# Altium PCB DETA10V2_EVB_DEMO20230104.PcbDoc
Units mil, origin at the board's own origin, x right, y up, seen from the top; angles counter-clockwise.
Board outline 1164.03 x 1653.03 mil, 2 copper layers (Top Layer, Bottom Layer), stack 61.855 mil thick; 50 components, 41 nets, 190 pads, 76 vias.
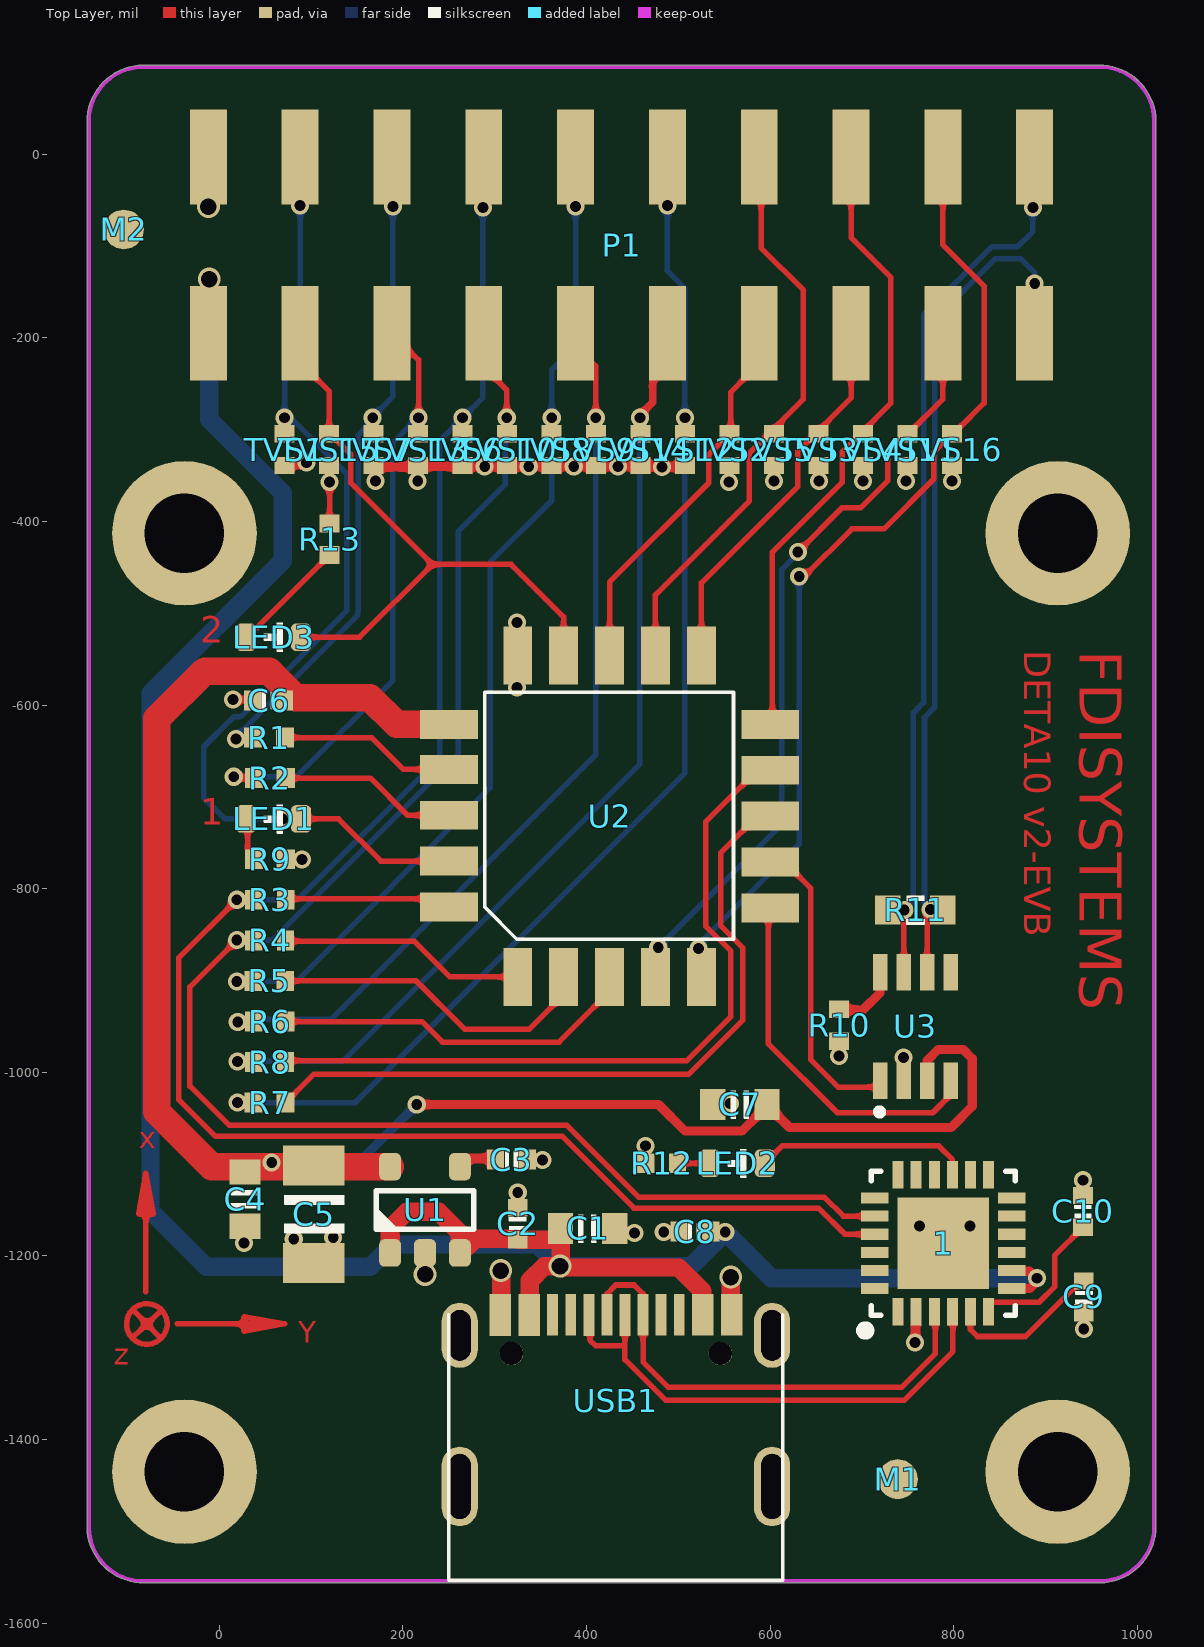
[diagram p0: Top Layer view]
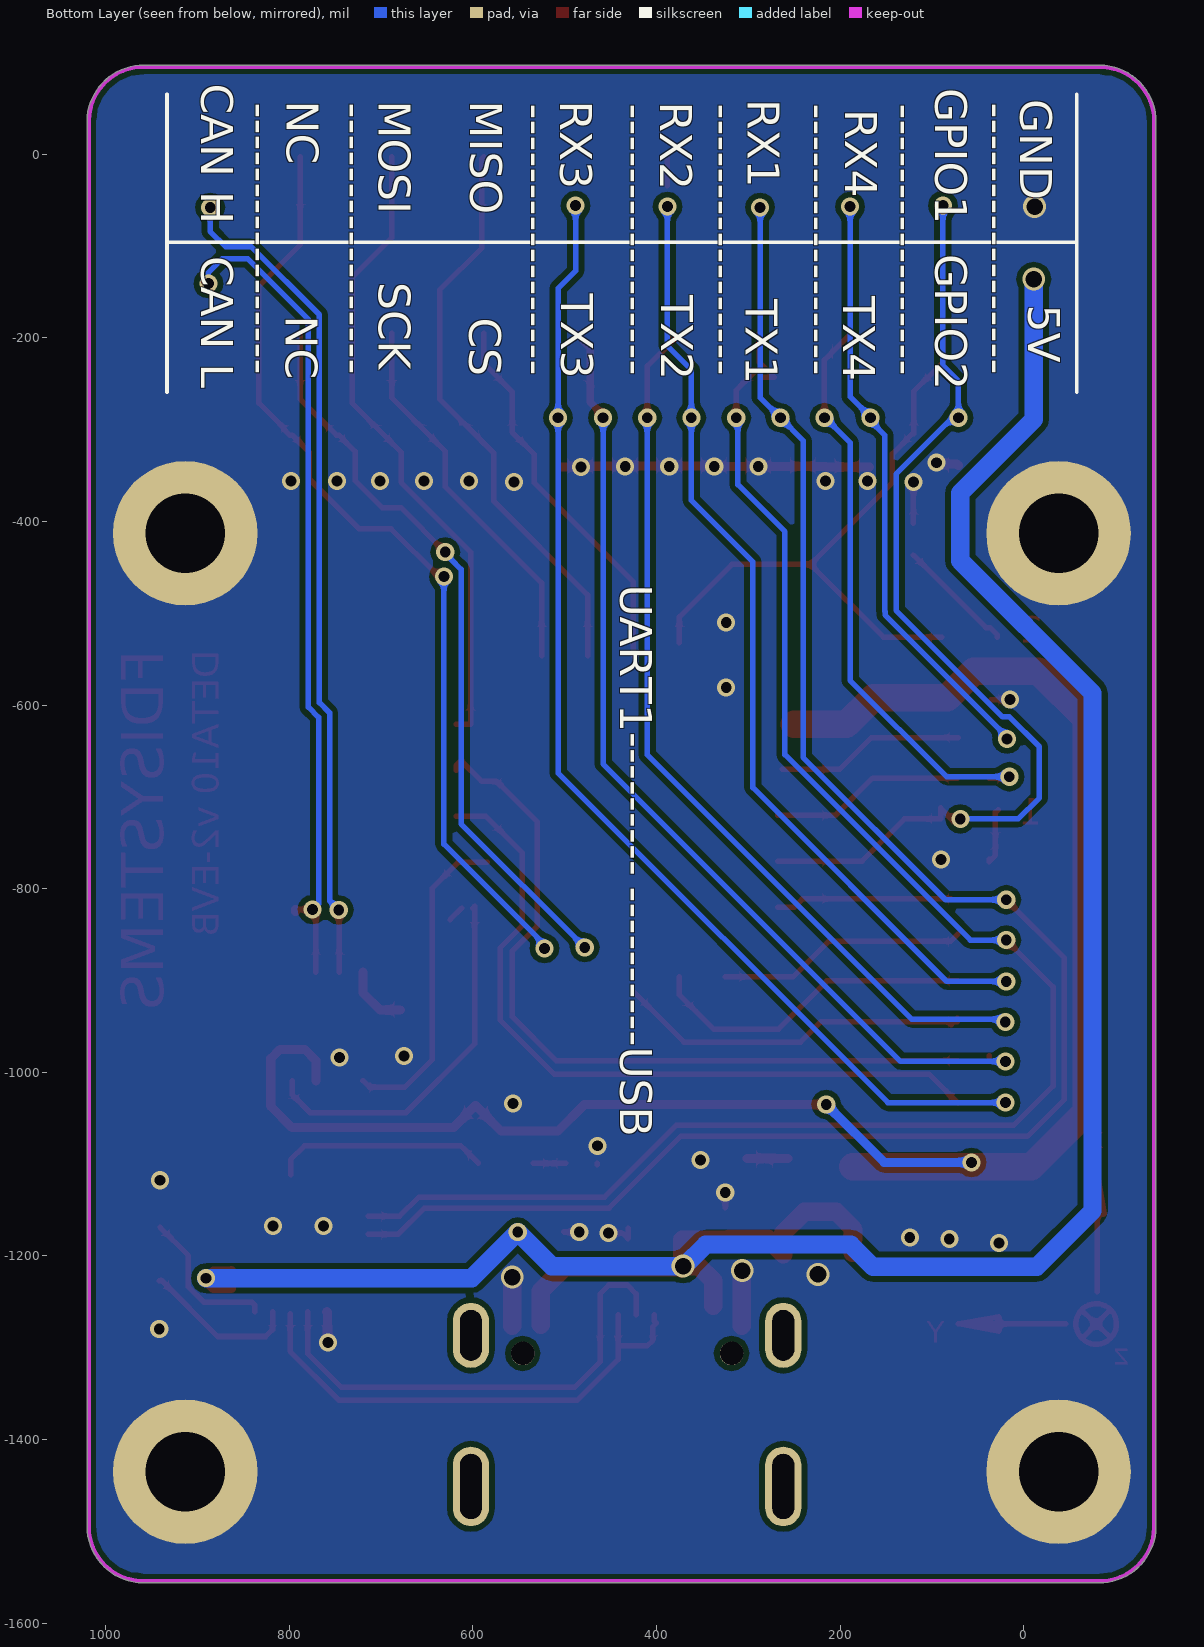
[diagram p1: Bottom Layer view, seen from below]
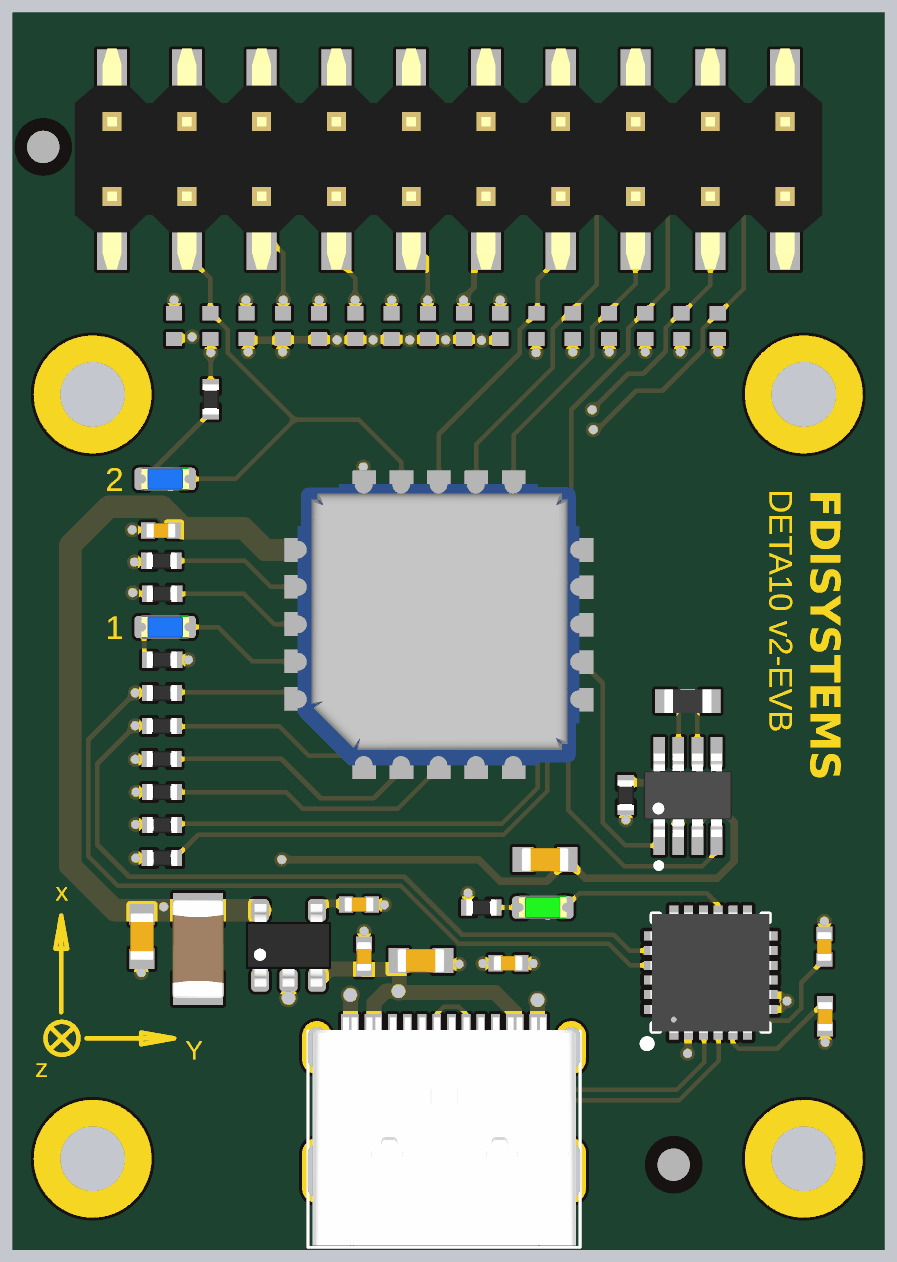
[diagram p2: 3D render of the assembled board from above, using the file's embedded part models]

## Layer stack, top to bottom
Top Solder: solder mask 0.4, Solder Resist, Dk 3.5
Top Layer: signal copper 1.4
Dielectric 1: dielectric 59.0551, FR-4, Dk 4.8
Bottom Layer: signal copper 1.4
Bottom Solder: solder mask 0.4, Solder Resist, Dk 3.5

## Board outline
-144.01,-1495.02 cw(c-142,-1495) -143.73,-1493.97 cw(c-142,-1493) -143.98,-1493 -143.98,34.65 cw(c-142,35) -144.01,34.98 cw(c-82.5,35.5) -83.02,97.01 cw(c-83,95) -82.65,96.98 957.65,96.98 cw(c958,95) 957.98,97.01 cw(c958.5,35.5) 1020.01,36.02 cw(c1018,36) 1020.01,36 cw(c1018,36) 1019.98,35.65 1019.98,-1493.64 cw(c1018,-1494) 1020.01,-1493.98 cw(c958.5,-1494.5) 1020.02,-1494.5 cw(c958.5,-1494.5) 959.02,-1556.01 cw(c959,-1554) 958.67,-1555.98 -81.65,-1555.98 cw(c-82,-1554) -81.98,-1556.01 cw(c-82.5,-1494.5)

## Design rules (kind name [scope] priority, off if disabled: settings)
Clearance [All] p1: gap=6 ignorepadtopadclearanceinfootprint=FALSE except(0: Arc-Hole Track-Hole SMDPad-Hole THPad-Hole Via-Hole Fill-Hole Poly-Hole Region-Hole Text-Hole; 5: SMDPad-SMDPad THPad-THPad)
HoleSize [All] p1: absolutevalues=TRUE maxlimit=500 minlimit=1 maxpercent=80.000 minpercent=20.000
MinimumSolderMaskSliver [All] p1: minsoldermaskwidth=6
PlaneConnect [All] p1: planeconnectstyle=Direct reliefexpansion=20 reliefentries=4 reliefconductorwidth=10 reliefairgap=10
PolygonConnect [All] p1: connectstyle=Direct reliefconductorwidth=10 reliefentries=4 polygonreliefangle="90 Angle" airgapwidth=10
RoutingVias [All] p1: holewidth=28 width=50 viastyle="Through Hole" minholewidth=28 minwidth=50 maxholewidth=28 maxwidth=50
SilkToSolderMaskClearance [IsPad] p1: minsilkscreentomaskgap=1 clearancetoexposedcopper=TRUE
SolderMaskExpansion [All] p1: expansion=4
Width [All] p1: maxlimit=30 minlimit=5 preferedwidth=8
26 further rules are at their usual default settings.

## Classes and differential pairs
component class FDI_DETA_LDO: C1 C2 C3 C4 U1
component class FDI_DETA_MAIN: C5 C6 C7 D? LED1 LED3 M1 M2 P1 P? R1 R2 R3 R4 R5 R6 R7 R8 R9 R10 R11 R13 TVS1 TVS2 TVS3 TVS4 TVS5 TVS6 TVS7 TVS8 TVS9 TVS10 TVS11 TVS12 TVS13 TVS14 TVS15 TVS16 U2 U3
component class FDI_DETA_USB: 1 C8 C9 C10 LED2 R12 USB1

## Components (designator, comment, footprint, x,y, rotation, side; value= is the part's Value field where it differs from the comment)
1 "CH9102F" QFN24_4X4 788.5,-1186.16 r90 top value=Value
C1 "10uF" C0603 401,-1172 r180 top
C2 "2.2uF" C0402 325,-1164.86 r270 top
C3 "470P" C0402 318,-1095 r180 top
C4 "10uF" C0603 26,-1138 r90 top locked
C5 "22uF" C1206 103,-1154.49 r270 top
C6 "0.1uF" C0402 53.64,-595 r0 top
C7 "10uF" C0603 567,-1037 r180 top value=100nF
C8 "1uF" C0402 518,-1173.5 r0 top
C9 "0.1uF" C0402 941.5,-1244.48 r90 top
C10 "0.1uF" C0402 940.5,-1151.48 r270 top
LED1 "LED_blue" LED_0603_BLUE 59,-724 r180 top
LED2 "LED_green" LED_0603_GREEN 564,-1099 r180 top
LED3 "LED_blue" LED_0603_BLUE 59,-526 r180 top
M1 "MARK" MARK_POINT 739,-1443 r0 top
M2 "MARK" MARK_POINT -104,-82 r0 top
P1 "MHDR2X10" HEAD_2.54_20 -12,-195.13 r0 top
R1 "100" RES0402#1 71.29,-635.31 r180 top value=1K
R2 "100" RES0402#1 37.64,-679.5 r0 top value=1K
R3 "100" RES0402#2 37.64,-812.06 r0 top value=1K
R4 "100" RES0402#2 37.35,-856.25 r0 top value=1K
R5 "100" RES0402#2 71.65,-900.44 r180 top value=1K
R6 "100" RES0402#2 37.64,-944.63 r0 top value=1K
R7 "100" RES0402#1 72,-1033 r180 top value=1K
R8 "100" RES0402#2 72,-988.81 r180 top value=1K
R9 "1K" RES0402#1 37.64,-767.88 r0 top
R10 "1K" RES0402#2 675,-966 r90 top
R11 "120R 1/10W" RES0603 758,-823 r0 top
R12 "1K" RES0402#2 499,-1099 r180 top
R13 "1K" RES0402#1 120,-436.65 r90 top
TVS1 "PTUC0521NC/5V" ESD_0402 71,-304.35 r270 top
TVS2 "PTUC0521NC/5V" ESD_0402 555.67,-304.35 r270 top
TVS3 "PTUC0521NC/5V" ESD_0402 652.6,-304.35 r270 top
TVS4 "PTUC0521NC/5V" ESD_0402 701.07,-304.35 r270 top
TVS5 "PTUC0521NC/5V" ESD_0402 604.13,-304.35 r270 top
TVS6 "PTUC0521NC/5V" ESD_0402 264.87,-304.35 r270 top
TVS7 "PTUC0521NC/5V" ESD_0402 167.94,-339 r90 top
TVS8 "PTUC0521NC/5V" ESD_0402 361.8,-304.35 r270 top
TVS9 "PTUC0521NC/5V" ESD_0402 410.27,-304.35 r270 top
TVS10 "PTUC0521NC/5V" ESD_0402 313.33,-304.35 r270 top
TVS11 "PTUC0521NC/5V" ESD_0402 749.53,-304.35 r270 top
TVS12 "PTUC0521NC/5V" ESD_0402 507.2,-304.35 r270 top
TVS13 "PTUC0521NC/5V" ESD_0402 216.4,-304.35 r270 top
TVS14 "PTUC0521NC/5V" ESD_0402 458.73,-304.35 r270 top
TVS15 "PTUC0521NC/5V" ESD_0402 119.47,-339 r90 top
TVS16 "PTUC0521NC/5V" ESD_0402 798,-304.35 r270 top
U1 "RT9193-33GB" SOT23-5 224,-1149.68 r90 top locked
U2 "FDI_DETA10V2" FDI_DETA 425,-721 r90 top
U3 "MAX3051" SOT23-8 757,-952 r90 top
USB1 "Type-C" TYPE-C_SOCKET_16P 248.5,-1549.98 r90 top locked

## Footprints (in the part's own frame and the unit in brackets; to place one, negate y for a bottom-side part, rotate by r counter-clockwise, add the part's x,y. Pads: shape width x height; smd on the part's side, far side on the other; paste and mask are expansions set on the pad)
C0402 [mm]
  rect 0.48x0.55 smd: 1(-0.44,0) 2(0.44,0)
  silkscreen extent -0.17,-0.23 0.16,0.23, body extent -0.51,-0.25 0.49,0.25, height 0.5
C0603 [mm]
  rect 0.7x0.85 smd: 1(-0.75,-0.051) 2(0.75,-0.051)
  silkscreen extent -0.24,-0.43 0.24,0.33, body extent -0.8,-0.45 0.8,0.35, height 0.8
C1206 [mm]
  rect 1.1x1.7 smd: 1(-1.35,0) 2(1.35,0)
  silkscreen extent -0.52,-0.81 0.51,0.84, body extent -1.67,-0.87 2.65,0.88, height 1.4
ESD_0402 [mm]
  rect 0.48x0.55 smd: 1(0,0) 2(0.88,0)
  body extent -0.2,-0.38 1.09,0.38, height 0.6
FDI_DETA [mm] "9.5mm"
  rect 1.6x0.8 smd mask+0: 1(-4.445,2.54) 2(-4.445,1.27) 3(-4.445,0) 4(-4.445,-1.27) 5(-4.445,-2.54) 11(4.445,-2.54) 12(4.445,-1.27) 13(4.445,0) 14(4.445,1.27) 15(4.445,2.54)
  rect 0.8x1.6 smd mask+0: 6(-2.54,-4.445) 7(-1.27,-4.445) 8(0,-4.445) 9(1.27,-4.445) 10(2.54,-4.445) 16(2.54,4.445) 17(1.296,4.445) 18(0.026,4.445) 19(-1.244,4.445) 20(-2.514,4.445)
  silkscreen extent -3.4,-3.43 3.43,3.45, body extent -4.78,-4.78 4.78,4.8, height 2.29
HEAD_2.54_20 [mm]
  rect 1.02x2.62 smd: 1(0,4.88) 2(2.54,4.88) 3(5.08,4.88) 4(7.62,4.88) 5(10.16,4.88) 6(12.7,4.88) 7(15.24,4.88) 8(17.78,4.88) 9(20.32,4.88) 10(22.86,4.88) 11(22.86,0) 12(20.32,0) 13(17.78,0) 14(15.24,0) 15(12.7,0) 16(10.16,0) 17(7.62,0) 18(5.08,0) 19(2.54,0) 20(0,0)
  body extent -1.27,-1.29 24.13,6.21, height 9.7
LED_0603_BLUE [mil]
  rrect50% 22x30 smd: 1(-30,0) 2(30,0)
  silkscreen extent -10,-16 10,16, body extent -32,-16 32,16, height 24
LED_0603_GREEN [mil]
  rrect50% 22x30 smd: 1(-30,0) 2(30,0)
  silkscreen extent -10,-16 10,16, body extent -32,-16 32,16, height 24
MARK_POINT [mm] "MARK_POINT"
  round 1.1 smd mask+0.43: 1(0,0)
QFN24_4X4 [mil]
  rect 30x12 smd mask+5: 1(-74.5,49.21) 2(-74.5,29.53) 3(-74.5,9.84) 4(-74.5,-9.84) 5(-74.5,-29.53) 6(-74.5,-49.21) 13(74.5,-49.21) 14(74.5,-29.53) 15(74.5,-9.84) 16(74.5,9.84) 17(74.5,29.53) 18(74.5,49.21)
  rect 12x30 smd mask+5: 7(-49.21,-74.5) 8(-29.53,-74.5) 9(-9.84,-74.5) 10(9.84,-74.5) 11(29.53,-74.5) 12(49.21,-74.5) 19(49.21,74.5) 20(29.53,74.5) 21(9.84,74.5) 22(-9.84,74.5) 23(-29.53,74.5) 24(-49.21,74.5)
  rect 100x100 smd mask+5: 25(0,0)
  silkscreen extent -100,-78 78,90, body extent -80,-80 80,80, height 30
RES0402#1 [mm]
  rect 0.5x0.55 smd: 1(0,0) 2(0.88,0)
  body extent -0.09,-0.27 0.96,0.28, height 0.4
RES0402#2 [mm]
  rect 0.48x0.55 smd: 1(0,0) 2(0.88,0)
  body extent -0.09,-0.27 0.96,0.28, height 0.4
RES0603 [mm]
  rect 0.7x0.8 smd: 1(-0.762,0) 2(0.762,0)
  silkscreen extent -0.24,-0.39 0.24,0.39, body extent -0.8,-0.4 0.8,0.4, height 0.45
SOT23-5 [mil]
  rrect50% 30x24 smd: 1(-47,38) 2(-47,0) 3(-47,-38) 4(47,-38) 5(47,38)
  silkscreen extent -21,-53 21,53, body extent -55,-57 55,57, height 57
SOT23-8 [mm]
  rect 1x0.4 smd: 1(-1.45,0.95) 2(-1.45,0.3) 3(-1.45,-0.35) 4(-1.45,-1) 5(1.55,-1) 6(1.55,-0.35) 7(1.55,0.3) 8(1.55,0.95)
  silkscreen extent -2.37,0.91 -2.25,1.02, body extent -1.34,-1.53 1.49,1.47, height 1.2
TYPE-C_SOCKET_16P [mm]
  oval 2.2x1 hole 0.6 slot 1.8 at 0 deg: 0(2.514,-0.339) 0(2.514,-8.979)
  oval 1.8x1 hole 0.6 slot 1.4 at 0 deg: 0(6.694,-8.979) 0(6.694,-0.339)
  rect 1.15x0.3 smd: A1(7.258,-1.309) A4(7.258,-2.109) A5(7.259,-3.409) A6(7.259,-4.41) A7(7.258,-4.909) A8(7.259,-5.909) A9(7.259,-7.209) A12(7.259,-8.009) B1(7.259,-7.71) B4(7.259,-6.909) B5(7.259,-6.409) B6(7.259,-5.408) B7(7.258,-3.91) B8(7.259,-2.909) B9(7.258,-2.409) B12(7.258,-1.608)
  round 0.65 hole 0.65 unplated: ""(6.194,-1.769) ""(6.194,-7.549)
  silkscreen extent -0.09,-9.28 7.26,-0.04, body extent -0.03,-9.15 7.72,-0.2, height 3.26

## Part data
1: "Imported"
C1 C2 C3 C4: library part Cap1, "贴片瓷介电容"
C5: library part "Cap Pol1", "Polarized Capacitor (Radial)"
C6 C8 C9 C10: library part C1
C7: library part CAP, "Capacitor"
LED1 LED2 LED3: library part LED
M1 M2: "Photo Mark Point"
P1: "Header, 10-Pin, Dual row"
R1 R2 R3 R4 R5 R6 R7 R8: library part Res1, "Resistor"
R9 R10 R11 R12 R13: library part R
TVS1 TVS2 TVS3 TVS4 TVS5 TVS6 TVS7 TVS8 TVS9 TVS10 TVS11 TVS12 TVS13 TVS14 TVS15 TVS16: library part Varistor_0, "双向400瓦瞬态抑制器/5V", Part Number=110130100560
U1: library part MIC5205, "150mA Low-Noise LDO Regulator"
U3: library part CAN
USB1: library part "Type-C Socket", "USB 3.1  单排16PIN四脚插板(L=7.35) 一体式MD"

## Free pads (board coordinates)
  round 157.48 hole 86.61: 5(-38,-1435) 5(-38,-413) 5(913,-1435) 5(913,-413)

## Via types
v1: diameter 19.68, hole 11.81, Top Layer to Bottom Layer, tented both sides, 70 vias
v2: diameter 25, hole 18, Top Layer to Bottom Layer, tented both sides, 6 vias

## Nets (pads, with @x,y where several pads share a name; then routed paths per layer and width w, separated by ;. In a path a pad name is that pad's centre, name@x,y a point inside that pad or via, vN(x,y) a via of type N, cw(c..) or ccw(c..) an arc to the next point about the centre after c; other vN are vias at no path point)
CAN_H: P1.10 R11.1 U3.7 | length 907.7
  Top Layer w6: U3.7 745.59,-890.57 745.59,-823.41 v1(746,-823)
  Bottom Layer w6: v1(746,-823) 756,-813 756,-608.34 767.16,-597.18 767.16,-174.84 841,-101 869,-101 886,-84 v1(886,-58)
CAN_L: P1.11 R11.2 U3.6 | length 890.8
  Top Layer w6: U3.6 770.78,-826.22 774.31,-822.69 R11.2@789,-822.69
  Top Layer w10: R11.2@793,-824.66 R11.2@793,-822.69
  Bottom Layer w6: v1(774.41,-822.59) 768,-816.19 768,-613.31 779.16,-602.15 779.16,-179.81 844.97,-114 873,-114 888,-129 v1(888,-141)
CAN_RX: U2.6 U3.4 | length 423.8
  Top Layer w6: U2.6 598,-819.01 598,-969 673,-1044 777,-1044 796.37,-1024.63 U3.4 ; U2.6@612,-821 U2.6@624.75,-833.75
CAN_TX: U2.7 U3.1 | length 349.1
  Top Layer w6: U2.7@584.24,-771 U2.7 615.74,-771 644,-799.26 644,-986 674,-1016 712.68,-1016 U3.1
D+: 1.3 USB1.A6 USB1.B6 | length 534.7
  Top Layer w6: USB1.A6 422.12,-1241.19 431.72,-1231.59 451.82,-1231.59 461.42,-1241.19 USB1.B6 461.42,-1315.42 489,-1343 743,-1343 779.78,-1306.22 1.3@779.78,-1261
D-: 1.4 USB1.A7 USB1.B7 | length 554.2
  Top Layer w6: USB1.B7 402.42,-1270.58 400,-1273 403.87,-1276.87 403.87,-1291.87 410,-1298 438.26,-1298 ; USB1.A7 441.77,-1312.74 486.03,-1357 745.97,-1357 799,-1303.97 1.4@799,-1263
GND: 1.2 1.25 C1.1 C2.1 C3.1 C4.1 C5.2 C6.1 C7.2 C8.1 C9.1 C10.1 P1.1 pad.5 R9.2 R10.1 R12.2 R13.2 TVS1.2 TVS2.2 TVS3.2 TVS4.2 TVS5.2 TVS6.2 TVS7.1 TVS8.2 TVS9.2 TVS10.2 TVS11.2 TVS12.2 TVS13.2 TVS14.2 TVS15.1 TVS16.2 U1.2 U2.15 U3.2 USB1.A1 USB1.A12 USB1.B1 USB1.B12 | length 657.8
  Top Layer w6: v1(15,-594) 35.32,-594 C6.1 ; R13.2 v1(120,-357) ; C2.1 v1(325,-1130.86) ; C1.1 430.53,-1180.53 431,-1181 437,-1175 v1(452,-1175) ; R12.2@464.35,-1100.38 R12.2 ; v1(484,-1174) 500.18,-1174 C8.1 ; USB1.B1 552.02,-1255.02 USB1.B1@554.04,-1253
  Top Layer w10: TVS1.2 72.5,-337.5 93.5,-337.5 v1(95,-336) ; TVS7.1@167.94,-340.65 214.78,-340.65 215.43,-340 v1(289,-340) v1(337,-340) 337.5,-339.5 361.3,-339.5 361.8,-340 362.3,-339.5 385.5,-339.5 v1(386,-340) 386.5,-339.5 409.77,-339.5 410.27,-340 410.77,-339.5 433.5,-339.5 v1(434,-340) 434.5,-339.5 458.23,-339.5 458.73,-340 458.91,-339.82 481.18,-339.82 v1(482,-340.65) TVS12.2@503,-340.65 ; v1(757.5,-1294.16) 758.24,-1293.42 758.24,-1261.39 1.2
  Top Layer w20: USB1.B12@307,-1276 v2@307,-1219 ; USB1.B1@557,-1276 v2(557,-1223) v2@557,-1220.77
  other v1: 941.5,-1279.48 27,-1186 81,-1181.36 124,-1180 762.5,-1167.16 817.5,-1167.16 940.5,-1117.48 352,-1095.5 464,-1080 556,-1034 745,-984 675,-982 90,-768 324,-581 324,-510 555,-357 170,-356 216,-356 604,-356 653,-356 701,-356 748,-356 798,-356
  other v2: 224,-1220 306.5,-1216 -12,-57
GPIO1: LED1.1 P1.2 TVS1.1 U2.19 | length 1083.3
  Top Layer w6: v1(69,-724) 78.49,-724 90.49,-712 90.49,-724 130,-724 175.99,-769.99 U2.19 U2.19@268.01,-769.99
  Bottom Layer w6: v1(69,-724) 6,-724 -17,-701 -17,-645.35 15.51,-612.84 22.8,-612.84 138.84,-496.8 138.84,-348.49 77.35,-287 v1(71,-287) 71,-247 88,-230 v1(88,-56)
GPIO2: LED3.1 P1.19 TVS15.2 U2.14 | length 682.7
  Top Layer w6: P1.19 88,-226.62 119.47,-258.09 TVS15.2 120.85,-304.35 143,-326.5 143,-357.65 232.11,-446.76 ; LED3.1 152.87,-526 232.11,-446.76 ; U2.14@375,-532 375,-504 317.76,-446.76 232.11,-446.76
GPS_USART3_RX: P1.6 R7.2 TVS12.1 | length 1261.9
  Bottom Layer w6: v1(19.64,-1033) 148,-1033 507,-674 v1(507,-287) 507,-146.2 488,-127.2 v1(488,-56)
GPS_USART3_TX: P1.15 R8.2 TVS14.1 | length 1050.9
  Top Layer w6: R8.2@37.35,-983.38 R8.2@37.35,-982
  Top Layer w8: v1(458,-287) 458,-283.95 471.92,-270.03 471.92,-211.2 P1.15
  Bottom Layer w6: v1@20,-988 134,-988 458,-664 v1@458,-291
  other v1: 19.64,-988
Net1_5: 1.5 C9.2 | length 170.7
  Top Layer w6: 1.5 818.03,-1280.16 825.56,-1287.69 877.97,-1287.69 C9.2@939.31,-1226.35 ; C9.2@940.12,-1227.16 C9.2
Net1_6: 1.6 C10.2 | length 165
  Top Layer w6: 1.6 837.71,-1253.37 840.71,-1250.37 892.93,-1250.37 909.67,-1233.63 909.67,-1199.63 C10.2
Net1_15: 1.15 LED2.1 | length 235
  Top Layer w6: LED2.1 612.84,-1080.16 783.5,-1080.16 798.34,-1095 1.15
NetC3_2: C3.2 U1.4 | length 44
  Top Layer w10: U1.4@257,-1093.68 C3.2@301,-1093.68
NetLED1_2: LED1.2 R9.1 | length 63.8
  Top Layer w6: LED1.2@27.64,-713.75 30.8,-716.91 30.8,-763.8 37.64,-770.64 R9.1
NetLED2_2: LED2.2 R12.1 | length 35
  Top Layer w6: R12.1 LED2.2
NetLED3_2: LED3.2 R13.1 | length 129.6
  Top Layer w6: LED3.2 29,-523.35 36.81,-515.54 41.1,-515.54 R13.1
NetR1_1: R1.1 U2.17 | length 206.1
  Top Layer w6: R1.1 165.78,-635.31 200.46,-669.99 U2.17 U2.17@262.99,-669.99
NetR2_2: R2.2 U2.18 | length 212.5
  Top Layer w6: R2.2 164.47,-679.5 204.96,-719.99 U2.18 U2.18@268.01,-719.99
NetR3_2: R3.2 U2.20 | length 192.3
  Top Layer w6: R3.2@79.46,-811 241.02,-811 U2.20 U2.20@268.01,-819.99
NetR4_2: R4.2 U2.1 | length 272.2
  Top Layer w6: R4.2@72,-849.67 79.33,-857 212,-857 251,-896 U2.1
NetR5_1: R5.1 U2.2 | length 360.3
  Top Layer w6: R5.1 214.44,-900.44 267,-953 337.72,-953 375,-915.72 U2.2
NetR6_2: R6.2 U2.3 | length 394.2
  Top Layer w6: R6.2 R6.2@75.58,-944.63 ; R6.2@72.29,-941.33 73.93,-942.98 R6.2@75.58,-944.63 ; R6.2@78.96,-948 R6.2@75.58,-944.63 ; U2.3@425,-912 370,-967 243,-967 220.63,-944.63 R6.2@75.58,-944.63
NetR7_1: R7.1 U2.8 | length 816
  Top Layer w6: R7.1 103,-1002 511.32,-1002 570,-943.32 570,-864.03 546,-840.03 546,-761 586,-721 U2.8 U2.8@617.99,-721
NetR8_1: R8.1 U2.9 | length 852.3
  Top Layer w6: R8.1@72,-987.17 509.19,-987.17 557,-939.35 557,-868 530,-841 530,-727 574.25,-682.75 590.49,-682.75 612,-661.24 612,-660 617.99,-665.99 U2.9@617.99,-671
NetR10_2: R10.2 U3.8 | length 70.8
  Top Layer w10: R10.2@679,-932 701,-932 719.66,-913.34 719.66,-891.04 U3.8
SPI_MISO: P1.7 TVS5.1 U2.12 | length 629.6
  Top Layer w6: U2.12 475,-479.84 577.16,-377.68 577.16,-325.63 636,-266.78 636,-148 590.08,-102.08 590.08,-5.08 P1.7
SPI_MOSI: P1.8 TVS4.1 U2.10 | length 705
  Top Layer w6: U2.10@617.99,-621 602.24,-621 602.24,-433.41 678.16,-357.49 678.16,-324.41 699.64,-302.93 731.17,-271.4 731.17,-133.92 688,-90.75 P1.8
SPI_NSS: P1.14 TVS2.1 U2.13 | length 418.4
  Top Layer w6: U2.13 425,-466 533,-358 533,-327 557,-303 557,-259 588,-228 P1.14
SPI_SCK: P1.13 TVS3.1 U2.11 | length 418.4
  Top Layer w6: U2.11 524.99,-467.01 630,-362 630,-323.5 688,-265.5 P1.13
STM_SWCLK: P1.9 TVS16.1 U2.5 | length 1034.6
  Top Layer w6: v1(631.5,-460) 637,-460 689,-408 723.65,-408 778.17,-353.48 778.17,-324.45 796.62,-306 799.38,-306 805.83,-299.55 805.83,-298.17 833,-271 833,-143.75 788,-98.75 P1.9
  Bottom Layer w6: v1(522,-865) 522,-860.98 631.5,-751.48 v1(631.5,-460)
STM_SWDIO: P1.12 TVS11.1 U2.4 | length 810.9
  Top Layer w6: v1(630,-433.41) 678.41,-385 698.65,-385 728.16,-355.49 728.16,-323.75 745.91,-306 748.66,-306 788,-266.66 P1.12
  Bottom Layer w6: v1(478,-864) 612.66,-729.34 612.66,-452.2 623.7,-441.16 624,-441.16 624,-439.41 v1(630,-433.41)
UART2_RX: P1.5 R5.2 TVS8.1 | length 1066.3
  Top Layer w6: P1.5@388,-34.5 P1.5
  Bottom Layer w6: v1(19,-901) 83.78,-901 295,-689.78 295,-444 362,-377 v1(362,-287) 362,-235 388,-209 v1(388,-57)
UART2_TX: P1.16 R6.1 TVS9.1 | length 983.1
  Top Layer w6: P1.16 381,-202.13 410,-231.13 v1(410,-287)
  Bottom Layer w6: v1@20,-942 122,-942 410,-654 v1(410,-287)
  other v1: 20,-945
UART4_RX: P1.3 R1.2 TVS7.2 | length 650.8
  Bottom Layer w6: v1(18,-637) 18,-634.62 150.84,-501.78 150.84,-498.16 151.16,-497.84 151.16,-306.12 166.5,-290.78 166.5,-286.5 189,-264 v1(189,-57)
  other v1: 167,-287
UART4_TX: P1.18 R2.1 TVS13.1 | length 644
  Top Layer w6: v1(15.64,-678) 18.64,-678 17.14,-679.5 R2.1 ; P1.18 217,-224.13 v1@217,-286
  Bottom Layer w6: v1(15.64,-678) 84,-678 189,-573 189,-314 v1@217,-286
  other v1: 217,-287
USART1_RX: 1.21 P1.4 R3.1 TVS6.1 | length 1966.4
  Top Layer w6: v1(19,-812) -44,-875 -44,-1030 -4.16,-1069.84 373.61,-1069.84 451.55,-1147.78 652.78,-1147.78 681.32,-1176.32 1.21
  Bottom Layer w6: v1(19,-812) 85,-812 240.14,-656.86 240.14,-311.86 v1(265,-287) 287,-265 v1(287,-58)
USART1_TX: 1.20 P1.17 R4.1 TVS10.1 | length 1824.8
  Top Layer w6: v1(19,-856) -32,-907 -32,-1015 10.84,-1057.84 378.58,-1057.84 456.52,-1135.78 658.78,-1135.78 679.63,-1156.63 1.20 ; P1.17@283,-242.7 271.92,-242.7 288,-226.62 P1.17 ; P1.17@291,-235 313,-257 v1(313,-287)
  Bottom Layer w6: v1(19,-856) 57.97,-856 260,-653.97 260,-411 311.16,-359.84 311.16,-288.84 v1(313,-287)
VBUS: 1.7 1.8 C1.2 C2.2 C8.2 P1.20 U1.1 U1.3 USB1.A4 USB1.A9 USB1.B4 USB1.B9 | length 2770.9
  Top Layer w10: 1.7 882.64,-1235.37 890.01,-1228 890.01,-1224.29 882.41,-1216.69 864,-1216.69 1.8
  Top Layer w20: U1.1 186,-1170 204,-1152 239,-1152 262,-1175 U1.3 262,-1198 278.64,-1181.36 C2.2@320.5,-1181.36 ; C2.2 372,-1182.18 372,-1211 v2(371,-1211) 354,-1211 338,-1227 USB1.B9@338,-1254 ; v2@373.14,-1213.59 374.14,-1212.59 500.4,-1212.59 526,-1238.19 USB1.B4@526,-1275
  Bottom Layer w20: v2(-11,-136) -11,-289 69,-369 69,-442.83 -75,-586.83 -75,-1151 -14.16,-1211.84 164.16,-1211.84 188.5,-1187.5 346.15,-1187.5 369.65,-1211 v2(371,-1211) 514,-1211 v1(551,-1174) 601.16,-1224.16 v1(890.5,-1224.16)
VCC3V3: C4.2 C5.1 C6.2 C7.1 U1.5 U2.16 U3.3 | length 2032.8
  Top Layer w10: v1(215,-1035) 478.35,-1035 507.35,-1064 569,-1064 597,-1036 621,-1060 697,-1060 ; 699,-1060 797,-1060 820,-1037 820,-985 810,-975 783,-975 770.78,-987.22 U3.3
  Top Layer w30: U1.5 103,-1102.68 57,-1102.68 28,-1102.68 -8.32,-1102.68 -68,-1043 -68,-615 -16.16,-563.16 54.16,-563.16 54.47,-563.17 66.77,-575.47 66.77,-575.77 83,-592 164,-592 193,-621 U2.16
  Bottom Layer w10: v1(57,-1098) 152,-1098 v1(215,-1035)
pads on no net: 1.1 1.9 1.10 1.11 1.12 1.13 1.14 1.16 1.17 1.18 1.19 1.22 1.23 1.24 M1.1 M2.1 U3.5 USB1. USB1.0 USB1.A5 USB1.A8 USB1.B5 USB1.B8
copper on no net: | length 691.4
  Top Layer w5.98: -93,-1260.02 -79,-1274.02 ; -80,-1239.02 -80,-1110.02 ; -65,-1288.02 -79,-1274.02 ; -65,-1261.02 -79,-1274.02 ; -57.07,-1271.03 ccw(c-79,-1274.02) -56.96,-1272.01 ; -46,-1274.02 71,-1274.02 ; -80,-1110.02 -87.71,-1154.07 -72,-1154.07 -80,-1110.02 ; -79,-1274.02 -93,-1287.02 -79,-1274.02 ; 71,-1274.02 26.95,-1282.02 26.95,-1266.31 71,-1274.02

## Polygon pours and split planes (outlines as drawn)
GND on Bottom Layer "Bottom Layer-GND 1" (solid, remove dead copper, pour order 20): -281,202 -245,166 1120,166 1120,-1594 1046,-1668 1033,-1655 -392,-1655
no net on Bottom Layer "Bottom Layer-No Net" (solid, remove dead copper, pour order 4): -379,151
GND on Bottom Layer "Bottom Layer-GND" (solid, remove dead copper, pour order 2): -304,182

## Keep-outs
Keep-Out Layer:
  lines w3.94: -142,-1493 -142,35 ; -83,95 958,95 ; -82,-1554 959,-1554 ; 1018,-1494 1018,36
  lines w4: -142,-1495 ccw(c-82.5,-1494.5) -82,-1554 ; -142,35 cw(c-82.5,35.5) -83,95 ; 958,95 cw(c958.5,35.5) 1018,36 ; 959,-1554 ccw(c958.5,-1494.5) 1018,-1494

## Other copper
Top Layer:
  region: 860,-1310
  region: 860,-1310
  text "DETA10 v2-EVB" at 867,-540 h50 r270
  text "FDISYSTEMS" at 922,-540 h78 r270
  text "2" at -21.05,-542 h50
  text "1" at -21,-740 h50
  text "x" at -88,-1090.02 h40
  text "Y" at 86,-1302.02 h40
  text "z" at -115,-1326.02 h40

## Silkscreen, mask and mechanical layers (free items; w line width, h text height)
Bottom Overlay:
  lines w3.94: -58,-259 -58,65 ; -58,-96 933,-96 ; 933,-259 933,65
  text "CAN H" at 907,77 h60 r90
  text "GPIO1" at 108,72 h60 r90
  text "GND" at 15,60 h60 r90
  text "RX1" at 312,60 h60 r90
  text "RX3" at 516,58 h60 r90
  text "MISO" at 614,58 h60 r90
  text "MOSI" at 714,58 h60 r90
  text "NC" at 814,58 h60 r90
  text "RX2" at 407,57 h60 r90
  text "-----------------" at 57,56 h60 r90
  text "-----------------" at 757,56 h60 r90
  text "-----------------" at 859,56 h60 r90
  text "-----------------" at 157,55 h60 r90
  text "-----------------" at 251,55 h60 r90
  text "-----------------" at 355,55 h60 r90
  text "-----------------" at 451,55 h60 r90
  text "-----------------" at 559,55 h60 r90
  text "RX4" at 206,49 h60 r90
  text "GPIO2" at 108,-109 h60 r90
  text "CAN L" at 907,-111 h60 r90
  text "SCK" at 714,-139.3 h60 r90
  text "TX3" at 515,-152.04 h60 r90
  text "TX2" at 406,-153.35 h60 r90
  text "TX4" at 208,-154.74 h60 r90
  text "TX1" at 314,-157.74 h60 r90
  text "5V" at 6.35,-164 h60 r90
  text "NC" at 815,-175.7 h60 r90
  text "CS" at 615,-177.94 h60 r90
  text "UART1---------" at 451,-469 h60 r90
  text "----------USB" at 451,-798 h60 r90
Top Solder:
  lines w5.98: -93,-1260.02 -79,-1274.02 ; -80,-1239.02 -80,-1110.02 ; -65,-1288.02 -79,-1274.02 ; -65,-1261.02 -79,-1274.02 ; -57.07,-1271.03 ccw(c-79,-1274.02) -56.96,-1272.01 ; -46,-1274.02 71,-1274.02 ; -80,-1110.02 -87.71,-1154.07 -72,-1154.07 -80,-1110.02 ; -79,-1274.02 -93,-1287.02 -79,-1274.02 ; 71,-1274.02 26.95,-1282.02 26.95,-1266.31 71,-1274.02
  text "DETA10 v2-EVB" at 867,-540 h50 r270
  text "FDISYSTEMS" at 922,-540 h78 r270
  text "2" at -21.05,-542 h50
  text "1" at -21,-740 h50
  text "x" at -88,-1090.02 h40
  text "Y" at 86,-1302.02 h40
  text "z" at -115,-1326.02 h40
Bottom Solder:
  text "V2.0/D01.23" at 985,-834 h50 r90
